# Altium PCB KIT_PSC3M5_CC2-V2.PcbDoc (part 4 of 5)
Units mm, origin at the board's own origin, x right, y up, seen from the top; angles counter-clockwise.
Board outline 131.5 x 87 mm, 6 copper layers (Top Layer, Int1 (GND), Int2 (Sign), Int3 (Sign), Int4 (PWR), Bottom Layer), stack 1.551 mm thick; 371 components, 253 nets, 1359 pads, 837 vias.
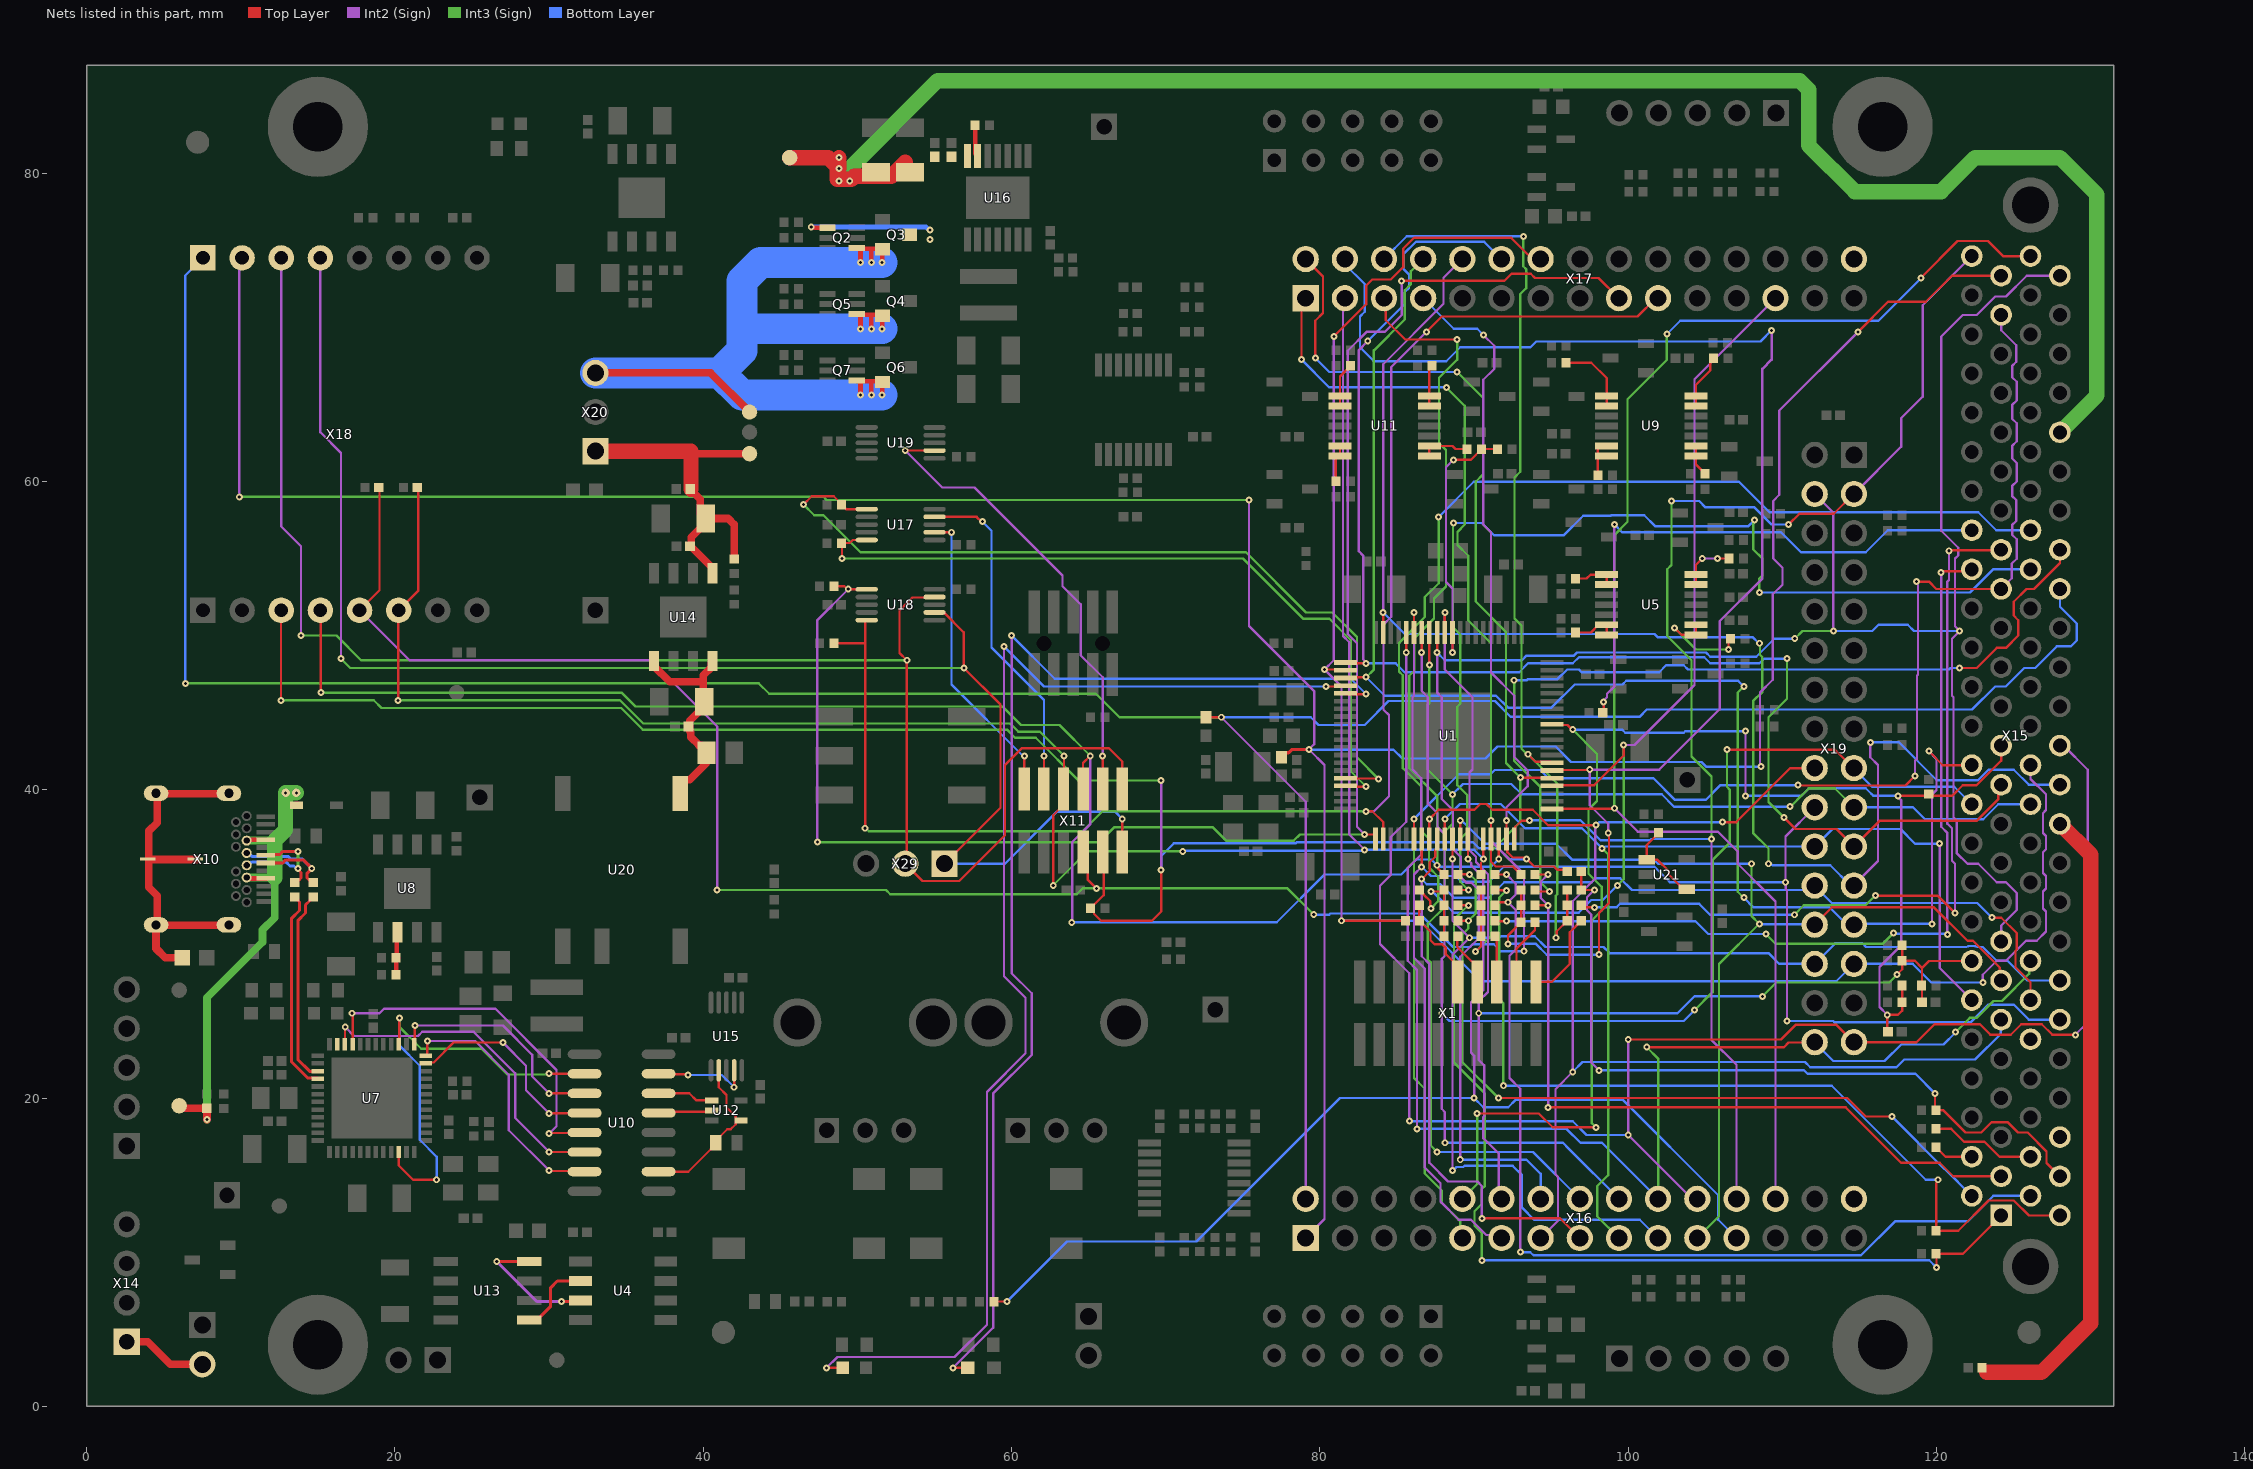
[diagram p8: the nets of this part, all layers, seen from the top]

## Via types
v1: diameter 0.45, hole 0.2, Top Layer to Bottom Layer, tented both sides, 833 vias
v2: diameter 0.55, hole 0.2, Top Layer to Bottom Layer, tented both sides, 4 vias

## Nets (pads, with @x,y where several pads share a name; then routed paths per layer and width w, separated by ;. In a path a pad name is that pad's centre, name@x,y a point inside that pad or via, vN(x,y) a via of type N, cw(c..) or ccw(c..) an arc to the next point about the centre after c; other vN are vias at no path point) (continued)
NetR135_1: R135.1 R146.2 U8.2 | length 3
  Top Layer w0.3: R146.2@20.07,28 R135.1@20.07,29.1 20.118,29.148 20.118,30.707 U8.2@20.165,30.755 U8.2@20.183,30.772 ; R135.1@20.085,29.085 20.195,29.085 R135.1@20.21,29.1
NetR140_1: R140.1 X15.A4 | length 2.6
  Top Layer w0.15: R140.1@119.97,16.8 119.97,16.78 120.185,16.565 120.205,16.565 120.575,16.195 X15.A4@122.285,16.195
NetR144_1: R144.1 X15.B4 | length 6.9
  Top Layer w0.15: R144.1@119.97,18 120.95,18 121.78,17.17 123.106,17.17 124.081,16.195 X15.B4@126.095,16.195
NetR148_1: R148.1 U21.1 U21.4 | length 5.6
  Top Layer w0.15: R148.1@101.97,37.2 101.97,37.18 101.2,36.41 U21.1@101.2,35.45 101.9,35.45 102.625,34.725 102.625,34.5 103.575,33.55 U21.4@103.8,33.55
NetU4_2: U4.2 U13.1 | length 5.1
  Top Layer w0.2: U13.1@28.7,5.595 29.2,5.595 30.1,6.495 30.1,7.7 30.535,8.135 U4.2@32.03,8.135
NetU4_3: U4.3 U13.4 | length 8.6
  Top Layer w0.2: v1(26.6,9.4) 28.695,9.4 U13.4@28.7,9.405 ; v1(30.8,6.8) 31.965,6.8 U4.3@32.03,6.865
  Int2 (Sign) w0.2: v1(26.6,9.4) 29.2,6.8 v1(30.8,6.8)
NetX14_1: X14.1 X30.2 | length 5.5
  Top Layer w0.5: X14.1@2.6,4.19 3.96,4.19 5.42,2.73 X30.2@7.5,2.73
OBD_RESET#: U7.47
OBD_RX: U7.46 U10.6 | length 21.9
  Top Layer w0.15: U7.46@16.75,23.5 16.763,23.513 16.763,24.587 v1(16.775,24.6) ; v1(30,16.5) 30.003,16.498 32.297,16.498 U10.6@32.3,16.495
  Int2 (Sign) w0.15: v1(16.775,24.6) 17.35,24.025 21.497,24.025 21.772,24.3 25.1,24.3 27.8,21.6 27.8,18.7 v1(30,16.5)
OBD_SWCLK: U7.22 U7.39 U10.2 | length 30.8
  Top Layer w0.15: U7.22@20.25,16.5 20.25,15.622 21.17,14.702 v1(22.7,14.702) ; U7.39@20.25,23.5 20.275,23.525 20.275,25.175 v1(20.3,25.2) ; v1(30,21.585) 30.005,21.58 32.295,21.58 U10.2@32.3,21.575
  Int3 (Sign) w0.15: v1(20.3,25.2) 20.3,24.6 21.7,23.2 25.6,23.2 27.275,21.525 29.94,21.525 v1(30,21.585)
  Bottom Layer w0.15: v1(20.3,25.2) 20.3,23.4 21.6,22.1 21.6,17.296 22.7,16.196 v1(22.7,14.702)
OBD_SWDIN: U7.36 U10.7 | length 16.8
  Top Layer w0.15: U7.36@22,22.75 22.025,22.75 22.1,22.825 v1(22.1,23.7) ; v1(30,15.3) 30.038,15.262 32.262,15.262 U10.7@32.3,15.225
  Int2 (Sign) w0.15: v1(22.1,23.7) 25.2,23.7 27.385,21.515 27.385,17.915 v1(30,15.3)
OBD_SWDIR: U7.37 U10.3 | length 14.9
  Top Layer w0.15: U7.37@21.25,23.5 21.275,23.525 21.275,24.675 v1(21.3,24.7) ; v1(30,20.3) 30.003,20.302 32.297,20.302 U10.3@32.3,20.305
  Int2 (Sign) w0.15: v1(21.3,24.7) 27,24.7 28.9,22.8 28.9,21.4 v1(30,20.3)
OBD_SWDOUT: U7.35 U10.4 | length 13.7
  Top Layer w0.15: U7.35@22,22.25 22.059,22.309 22.509,22.309 23.8,23.6 v1(27,23.6) ; v1(30,19) 30.018,19.018 32.283,19.018 U10.4@32.3,19.035
  Int2 (Sign) w0.15: v1(27,23.6) 28.5,22.1 28.5,20.5 v1(30,19)
OBD_TX: U7.45 U10.5 | length 23.7
  Top Layer w0.15: v1(17.2,25.5) 17.25,25.45 U7.45@17.25,23.5 ; v1(30,17.7) 30.033,17.732 32.267,17.732 U10.5@32.3,17.765
  Int2 (Sign) w0.15: v1(17.2,25.5) 19,25.5 19.3,25.8 26.5,25.8 30.475,21.825 30.475,18.175 v1(30,17.7)
OUT1A: R16.1 U5.1 U5.2 | length 7.1
  Top Layer w0.15: v1(103,50.5) 103.45,50.05 U5.1@104.4,50.05 U5.2@104.4,50.7 ; v1(106.5,49.1) 106.5,49.67 R16.1@106.63,49.8
  Int3 (Sign) w0.15: v1(103,50.5) 104.4,49.1 v1(106.5,49.1)
OUT1B: R41.1 U5.6 U5.7 | length 3.6
  Top Layer w0.15: U5.6@104.4,53.3 104.4,54.6 v1(104.8,55) ; v1(105.8,55) R41.1@106.53,55
  Int2 (Sign) w0.15: v1(104.8,55) v1(105.8,55)
OUT1C: R43.1 U5.8 U5.9 | length 2.9
  Top Layer w0.15: R43.1@96.57,53.7 97.3,53.7 97.55,53.95 U5.8@98.6,53.95 U5.9@98.6,53.3 U5.9@98.5,53.2
OUT1D: R45.1 U5.13 U5.14 | length 2.9
  Top Layer w0.15: R45.1@96.57,50.2 97.575,50.2 98.075,50.7 U5.13@98.6,50.7 U5.14@98.6,50.05
OUT2A: R55.1 U9.1 U9.2 | length 2
  Top Layer w0.15: U9.2@104.4,62.3 U9.1@104.4,61.65 104.4,61.09 104.97,60.52 R55.1@104.97,60.5
OUT2B: R57.1 U9.6 U9.7 | length 3.6
  Top Layer w0.15: U9.6@104.4,64.9 U9.7@104.4,65.55 104.4,66.275 105.315,67.19 105.315,67.785 R57.1@105.53,68
OUT2C: R59.1 U9.8 U9.9 | length 4.8
  Top Layer w0.15: R59.1@95.97,67.7 97.6,67.7 98.6,66.7 U9.8@98.6,65.55 U9.9@98.6,64.9
OUT2D: R61.1 U9.13 U9.14 | length 2.4
  Top Layer w0.15: R61.1@98.03,60.4 98.03,62.15 98.18,62.3 U9.13@98.6,62.3
OUT3A: R40.1 U11.1 U11.2 | length 3.2
  Top Layer w0.15: U11.1@87.1,61.65 U11.2@87.1,62.3 88.6,62.3 88.8,62.1 R40.1@89.53,62.1
OUT3B: R42.1 U11.6 U11.7 | length 2.7
  Top Layer w0.15: U11.6@87.1,64.9 U11.7@87.1,65.55 87.1,67.33 R42.1@87.27,67.5
OUT3C: R44.1 U11.8 U11.9 | length 2.9
  Top Layer w0.15: U11.9@81.3,64.9 U11.8@81.3,65.55 81.3,66.81 81.97,67.48 R44.1@81.97,67.5
OUT3D: R46.1 U11.13 U11.14 | length 2.5
  Top Layer w0.15: R46.1@81.03,60 81.03,61.5 81.18,61.65 U11.14@81.3,61.65 U11.13@81.3,62.3
P0_0_PFC_Relay1: R1.1 X15.A49 X16.1 X18.15 | length 206.4
  Top Layer w0.15: v1(114.9,69.7) 116.851,71.651 119.302,71.651 120.996,73.345 X15.A49@124.19,73.345
  Top Layer w0.2: R1.1@77.5,42.1 77.5,42.15 77.75,42.4 77.971,42.4 78.171,42.6 v1(79.3,42.6)
  Int2 (Sign) w0.15: v1(9.9,59) 9.9,74.32 X18.15@10.08,74.5 ; v1(75.4,58.8) 75.4,50.628 79.621,46.407 79.621,42.95 79.3,42.629 v1(79.3,42.6) 80.3,41.6 80.3,12.146 X16.1@79.312,11.158 ; v1(108.6,41.5) 108.55,41.55 108.55,46.314 109.375,47.139 109.375,52.675 110,53.3 110,54.4 109.4,55 109.4,58.728 109.8,59.128 109.8,64.6 v1(114.9,69.7)
  Int2 (Sign) w0.2: X16.1@79.076,10.922 X16.1@79.312,11.158
  Int3 (Sign) w0.15: v1(9.9,59) 47.8,59 48,58.8 v1(75.4,58.8)
  Bottom Layer w0.15: v1(79.3,42.6) 84.776,42.6 85.351,42.025 90.747,42.025 91.522,42.8 95.293,42.8 96.293,41.8 104.749,41.8 105.049,41.5 v1(108.6,41.5)
P0_1_ENPOW3: R2.2 X15.B33 X16.2 X18.16 | length 193.3
  Top Layer w0.15: R2.2@72.6,44.7 v1(73.6,44.7)
  Int2 (Sign) w0.15: v1(73.6,44.7) 79.076,39.224 X16.2@79.076,13.462
  Int3 (Sign) w0.15: v1(6.4,46.9) 43.6,46.9 44.275,46.225 65.475,46.225 67,44.7 v1(73.6,44.7)
  Bottom Layer w0.15: v1(6.4,46.9) 6.4,73.36 X18.16@7.54,74.5 ; v1(73.6,44.7) 79.4,44.7 79.9,44.2 82.9,44.2 84.45,45.75 91.35,45.75 92.375,44.725 100.725,44.725 101.2,45.2 122.3,45.2 123.8,46.7 124.482,46.7 125.682,47.9 126.4,47.9 127.8,49.3 128.7,49.3 129.1,49.7 129.1,50.764 128,51.864 X15.B33@128,53.025
P3_3_PFC_Overcurrent_Prot: U1.26 X15.A33 X15.A47 X16.9 | length 103.3
  Top Layer w0.15: U1.26@86.1,36.8 v1(86.1,38.1) ; v1(111,40.3) 111.023,40.277 117.977,40.277 v1(118.6,40.9) ; v1(118.7,53.5) 119.5,53.5 119.98,53.02 124.185,53.02 X15.A33@124.19,53.025
  Int2 (Sign) w0.15: v1(118.6,40.9) 118.6,41.876 118.725,42.001 118.725,47.397 118.8,47.472 118.8,53.305 118.7,53.405 v1(118.7,53.5) ; X15.A33@124.19,53.025 124.883,53.717 124.883,54.668 125.2,54.985 125.2,56.246 124.9,56.546 124.9,57.175 125.165,57.44 125.165,58.795 124.9,59.06 124.9,59.702 125.2,60.002 125.2,61.2 124.9,61.5 124.9,62.3 125.2,62.6 125.2,63.768 124.9,64.068 124.9,64.955 125.2,65.255 125.2,66.46 124.9,66.76 124.9,67.495 125.165,67.76 125.165,68.835 124.19,69.81 X15.A47@124.19,70.805
  Int3 (Sign) w0.15: v1(86.1,38.1) 86.1,21.3 86.8,20.6 86.8,15.1 87.9,14 87.9,13.207 89.11,11.997 89.11,11.048 X16.9@89.236,10.922
  Bottom Layer w0.15: v1(86.1,38.1) 89,41 91.068,41 91.343,41.275 94.295,41.275 94.83,40.74 101.631,40.74 103.031,39.34 105.02,39.34 105.98,40.3 v1(111,40.3)
P4_0_U1_H: U1.27 X15.B11 X16.11 X19.20 | length 87.5
  Top Layer w0.15: v1(86.6,35) U1.27@86.6,36.8
  Int2 (Sign) w0.15: v1(86.6,35) 86.1,34.5 86.1,29.1 86.8,28.4 86.8,15.5 87.821,14.479 87.821,13.286 89,12.107 89.793,12.107 90.789,11.111 91.587,11.111 X16.11@91.776,10.922 ; v1(110.3,25) 110.3,33.475 110.225,33.55 110.225,33.975 v1(110.2,34) 110.2,36.966 X19.20@112.096,38.862
  Bottom Layer w0.15: v1(86.6,35) 87.2,34.4 88.823,34.4 89.186,34.037 90.966,34.037 91.928,35 101.7,35 102.7,34 v1(110.2,34) ; v1(110.3,25) 113.295,25 113.37,24.925 122.234,24.925 123.369,26.06 125.011,26.06 125.986,25.085 X15.B11@128,25.085
P4_1_U1_L: U1.28 X15.A11 X16.13 X19.18 | length 87.3
  Top Layer w0.15: U1.28@87.1,36.7 U1.28@87.1,36.8 v1(87.1,38.1) 87.7,38.7 90.028,38.7 90.403,39.075 90.797,39.075 91.172,38.7 93.8,38.7 94.8,37.7 v1(97.9,37.7) ; v1(106.1,37.9) 107,37.9 110.502,41.402 X19.18@112.07,41.402
  Int2 (Sign) w0.15: X16.13@94.316,10.922 95.441,12.047 95.441,14.887 95.275,15.053 95.275,20.575 v1(96.4,21.7) 96.4,32.772 97.85,34.222 97.85,37.65 v1(97.9,37.7)
  Bottom Layer w0.15: v1(96.4,21.7) 97.033,22.333 111.467,22.333 111.8,22 117.4,22 117.9,22.5 122.5,22.5 124.16,24.16 124.16,25.055 X15.A11@124.19,25.085 ; v1(97.9,37.7) 97.938,37.7 98.138,37.9 v1(106.1,37.9)
P4_2_V1_H: U1.29 X15.B12 X16.15 X19.24 | length 80.7
  Top Layer w0.15: v1(86.6,34.2) 87.125,34.725 87.125,35.297 87.475,35.647 87.475,36.075 87.6,36.2 U1.29@87.6,36.8 ; v1(90.5,12.2) 95.578,12.2 X16.15@96.856,10.922 ; v1(123.6,31.7) 124.2,31.7 125.2,30.7 125.2,29.632 125.12,29.552 125.12,28.484 126.095,27.509 X15.B12@126.095,26.355
  Int2 (Sign) w0.15: v1(86.6,34.2) 86.6,29.2 87.1,28.7 87.1,15.8 88.313,14.587 90.213,14.587 90.5,14.3 v1(90.5,12.2)
  Bottom Layer w0.15: v1(86.6,34.2) 86.925,33.875 87.825,33.875 88.7,33 90.954,33 91.954,34 97.628,34 97.878,34.25 99.486,34.25 100.236,33.5 111.788,33.5 112.07,33.782 113.195,32.657 122.643,32.657 v1(123.6,31.7)
P4_3_V1_L: U1.30 X15.A12 X16.17 X19.22 | length 73.2
  Top Layer w0.15: U1.30@88.1,36.8 v1(88.1,38.1)
  Int2 (Sign) w0.15: v1(120.2,36.5) 120.2,28.44 X15.A12@122.285,26.355
  Int3 (Sign) w0.15: v1(98.3,36.2) 98.7,35.8 98.7,15 97.981,14.281 97.981,12.337 X16.17@99.396,10.922
  Bottom Layer w0.15: v1(88.1,38.1) 88.5,38.5 88.504,38.5 89.079,39.075 91.725,39.075 93.3,37.5 97,37.5 v1(98.3,36.2) ; v1@98.381,36.2 98.503,36.322 112.122,36.322 113.247,37.447 117.653,37.447 118.6,36.5 v1(120.2,36.5)
P4_4_W1_H: U1.31 X15.B13 X16.19 X19.28 | length 79.7
  Top Layer w0.15: v1(88.6,35.5) U1.31@88.6,36.8
  Int2 (Sign) w0.15: v1(88.6,15.3) 88.6,29.3 v1(89.7,30.4) 88.6,31.5 v1(88.6,35.5)
  Bottom Layer w0.15: v1(88.6,15.3) 88.638,15.3 88.863,15.525 89.297,15.525 89.372,15.6 92.5,15.6 93.1,15 93.1,12.9 93.893,12.107 100.751,12.107 X16.19@101.879,10.979 ; v1(89.7,30.4) 91.644,30.4 91.744,30.5 93.932,30.5 94.632,29.8 98.395,29.8 98.795,29.4 109.1,29.4 109.798,28.702 X19.28@112.07,28.702 ; X16.19@101.9,11 101.936,10.964 X16.19@101.936,10.922 ; X19.28@112.096,28.702 113.435,30.041 115.175,30.041 115.417,29.8 121.922,29.8 cw(c122.285,28.895) 122.648,29.8 123,29.8 123.9,28.9 124.6,28.9 125.875,27.625 X15.B13@128,27.625
P4_5_W1_L: U1.32 X15.A13 X16.21 X19.26 | length 66
  Top Layer w0.15: U1.32@89.1,36.8 v1(89.1,38) ; X19.26@112.07,31.242 113.195,32.367 119.833,32.367 122,30.2 122.359,30.2 124.097,28.462 124.097,27.718 X15.A13@124.19,27.625
  Int3 (Sign) w0.15: X16.21@104.476,10.922 105.891,12.337 105.891,28.691 v1(108.5,31.3) 108,31.8 v1(108,35.2)
  Bottom Layer w0.15: v1(89.1,38) 89.195,38 89.331,37.864 89.336,37.864 90.7,36.5 95.328,36.5 96.378,35.45 101.674,35.45 101.924,35.2 v1(108,35.2) ; v1(108.5,31.3) 108.529,31.271 112.041,31.271 X19.26@112.07,31.242
P7_0_SCB2_CLK: R60.1 R81.1 X15.A2 | length 50.9
  Top Layer w0.15: R60.1@88.95,31.5 v1(89.625,31.5) ; R81.1@88.95,34.5 88.962,34.512 v1(89.712,34.512) ; v1(91.575,20) 114.2,20 115.4,18.8 v1(117.1,18.8)
  Int2 (Sign) w0.15: v1(89.712,34.512) v1@89.779,34.446
  Int3 (Sign) w0.15: v1(89.712,34.512) 90.1,34.125 90.1,31.975 v1(89.625,31.5) 89.625,30.997 89.25,30.622 89.25,22.325 v1(91.575,20)
  Bottom Layer w0.15: v1(117.1,18.8) 120.5,15.4 120.54,15.4 X15.A2@122.285,13.655
P7_0_SCB2_SCL: R56.1 R141.1 X15.A1 | length 61.2
  Top Layer w0.15: R56.1@88.95,32.5 v1(89.625,32.5) ; v1(120,9) 120,9.87 R141.1@119.97,9.9 121.705,9.9 X15.A1@124.19,12.385
  Int3 (Sign) w0.15: v1(89.625,32.5) 88.7,31.575 88.7,22.3 90.7,20.3 90.7,14.3 90.5,14.1 90.5,13.133 90.025,12.658 90.025,11.724 90.5,11.249 v1(90.5,9.475)
  Bottom Layer w0.15: v1(90.5,9.475) 119.525,9.475 v1(120,9)
P7_0_U3_H/PFC_PWM_A_1: R88.1 X15.B34 | length 69.6
  Top Layer w0.15: R88.1@88.95,33.5 v1(89.625,33.5) ; X15.B34@126.09,54.29 X15.B34@126.095,54.295
  Int3 (Sign) w0.15: v1(88.65,57.3) 88.625,57.275 88.625,50.547 89.1,50.072 89.1,45.586 88.9,45.386 88.9,40.3 89.55,39.65 89.55,37.25 89.1,36.8 89.1,34.025 v1(89.625,33.5) ; v1(108.2,57.5) 108.133,57.433 108.133,57.27 108.1,57.237 108.1,55.604 108.7,55.004 108.7,53.903 108.5,53.703 v1(108.5,52.8)
  Bottom Layer w0.15: v1(88.65,57.3) 90.5,57.3 91.3,56.5 95.8,56.5 97.075,57.775 98.629,57.775 98.878,57.775 98.903,57.8 101.031,57.8 101.731,57.1 107.8,57.1 v1(108.2,57.5) ; v1(108.5,52.8) 122.169,52.8 123.664,54.295 X15.B34@126.095,54.295
P7_1_SCB2_MOSI: R62.1 R82.1 X15.B2 | length 62.2
  Top Layer w0.15: R62.1@91.35,32.4 91.35,32.475 91.575,32.7 v1(92.2,32.7) ; R82.1@91.35,34.5 v1(92.1,34.5)
  Int2 (Sign) w0.15: v1(92.1,34.5) 92.7,33.9 92.7,33.2 v1(92.2,32.7) 92.7,32.2 92.7,29.628 92.3,29.228 92.3,21.3 93,20.6 v1(93,10)
  Bottom Layer w0.15: v1(93,10) 93.647,10 93.85,9.797 115.102,9.797 117.305,12 122.016,12 123.671,13.655 X15.B2@126.095,13.655
P7_1_SCB2_SDA: R58.1 R142.1 X15.B1 | length 57.1
  Top Layer w0.15: R58.1@91.35,33.5 91.378,33.472 v1(92.098,33.472) ; v1(120.1,14.7) 120.1,14.605 119.97,14.475 R142.1@119.97,11.4 121.4,11.4 121.408,11.392 123.376,13.36 125.011,13.36 125.986,12.385 X15.B1@128,12.385
  Int3 (Sign) w0.15: v1(91.9,20.8) 91.9,26.144 91.623,26.42 91.623,32.997 v1(92.098,33.472)
  Bottom Layer w0.15: v1(91.9,20.8) 113.2,20.8 119.3,14.7 v1(120.1,14.7)
P7_1_U3_L/PFC_PWM_A_2: R89.1 X15.A34 | length 56
  Top Layer w0.15: R89.1@91.35,31.5 91.378,31.472 v1(92.098,31.472) ; v1(120.3,54.1) 120.367,54.167 122.157,54.167 X15.A34@122.285,54.295
  Int2 (Sign) w0.15: v1(120.3,54.1) 120.3,37.6 120.7,37.2 v1(120.7,30.6)
  Int3 (Sign) w0.15: v1(108.925,30.643) 109.568,30 116.5,30 v1(117.2,30.7)
  Bottom Layer w0.15: v1(92.098,31.472) 104.356,31.472 105.185,30.643 v1(108.925,30.643) ; v1(117.2,30.7) 117.25,30.65 120.65,30.65 v1(120.7,30.6)
P7_2_SCB2_MISO: R74.1 R83.1 X15.A3 | length 48.4
  Top Layer w0.15: R74.1@93.95,32.5 v1(94.8,32.5) ; R83.1@93.95,34.5 v1(94.8,34.5) ; v1(94.8,19.4) 114.1,19.4 117.7,15.8 120.2,15.8 121.075,14.925 X15.A3@124.19,14.925
  Int2 (Sign) w0.15: v1(94.8,19.4) v1(94.8,32.5) 94.325,32.975 94.325,34.025 v1(94.8,34.5)
P7_2_V3_H/PFC_PWM_B_1: R90.1 X15.B35 | length 57.1
  Top Layer w0.15: R90.1@93.95,33.5 94.05,33.4 v1(94.9,33.4) ; v1(121.5,47.9) 122.6,47.9 123.9,49.2 124.5,49.2 125.3,50 125.3,51 125,51.3 125,52.2 125.825,53.025 126.325,53.025 128,54.7 X15.B35@128,55.565
  Int3 (Sign) w0.15: v1(92.6,47.1) 92.6,41.872 94.3,40.172 94.3,34 v1(94.9,33.4)
  Bottom Layer w0.15: v1(92.6,47.1) 93.428,47.1 93.503,47.175 95.412,47.175 96.037,47.8 96.8,47.8 96.975,47.625 102.003,47.625 102.453,48.075 103.597,48.075 103.872,47.8 120.8,47.8 120.9,47.9 v1(121.5,47.9)
P7_3_SCB2_SEL0: R76.1 R87.1 R143.1 X15.B3 | length 48.6
  Top Layer w0.15: R87.1@96.95,34.7 R76.1@96.95,33.5 v1(97.8,33.5) ; v1(119.9,20.3) 119.9,19.27 R143.1@119.97,19.2 120.441,19.2 121.881,17.76 122.898,17.76 123.577,18.44 124.594,18.44 125.274,17.76 125.909,17.76 127.13,16.539 127.13,15.795 X15.B3@128,14.925
  Int2 (Sign) w0.15: v1(97.8,33.5) 97.325,33.025 97.325,32.176 97.6,31.901 97.6,22.3 v1(98.1,21.8)
  Bottom Layer w0.15: v1(98.1,21.8) 111.4,21.8 111.625,21.575 118.625,21.575 v1(119.9,20.3)
P7_3_V3_L/PFC_PWM_B_2: R92.1 X15.A35 | length 52.8
  Top Layer w0.15: R92.1@96.95,32.5 97.078,32.372 v1(97.8,32.372) ; v1(116.025,33.132) 120.068,33.132 v1(121.2,32) ; v1(120.8,55.5) 120.832,55.533 124.158,55.533 X15.A35@124.19,55.565 X15.A35@124.185,55.57
  Int2 (Sign) w0.15: v1(120.8,55.5) 120.8,53.6 120.7,53.5 120.7,37.8 121,37.5 121,35.4 121.2,35.2 v1(121.2,32)
  Int3 (Sign) w0.15: v1(110.775,31.892) 111.383,32.5 115.393,32.5 v1(116.025,33.132)
  Bottom Layer w0.15: v1(97.8,32.372) 99.244,32.372 99.472,32.6 104.597,32.6 105.305,31.892 v1(110.775,31.892)
P7_4_W3_H/PFC_PWM_C_1: R97.1 X15.B36 | length 70
  Top Layer w0.15: R97.1@86.363,33.587 R97.1@86.45,33.5 86.725,33.225 86.725,33.203 87.153,32.775 87.153,32.347 v1(87.2,32.3)
  Int3 (Sign) w0.15: v1(87.2,32.3) 87.675,32.775 87.675,34.353 87.075,34.953 87.075,36.825 86.575,37.325 86.575,40.201 85.375,41.401 85.375,47.425 85.125,47.675 85.125,49.525 86.8,51.2 86.8,52.5 87.7,53.4 v1(87.7,57.7)
  Bottom Layer w0.15: v1(87.7,57.7) 89.975,59.975 107.182,59.975 109.157,58 122.7,58 123.865,56.835 X15.B36@126.095,56.835
P7_5_W3_L/PFC_PWM_C_2: R98.1 X15.A36 | length 37
  Top Layer w0.15: R98.1@98.35,45 98.4,45.05 v1(98.4,45.7)
  Int2 (Sign) w0.15: v1(98.4,45.7) 98.4,45.781 98.621,46.002 98.621,46.221 99.1,46.7 v1(99.1,57.2)
  Bottom Layer w0.15: v1(99.1,57.2) 99.6,56.7 109.9,56.7 111.2,55.4 115.4,55.4 116.835,56.835 X15.A36@122.285,56.835
P7_7_KILL_2: C138.1 R32.1 R36.2 R162.1 U1.52 X15.A25 X16.10 | length 96.2
  Top Layer w0.15: v1(90.2,19) 94.2,19 95.1,18.1 v1(97.9,18.1) ; U1.52@95.225,44.275 95.306,44.194 96.057,44.194 96.351,43.9 v1(96.4,43.9) ; C138.1@116.86,24.3 116.8,24.36 v1(116.8,25.4) 117.5,25.4 117.77,25.67 R36.2@117.77,27.3 ; v1(117.5,39.6) 119.37,39.6 R162.1@119.5,39.73 119.63,39.6 121,39.6 121.694,40.294 122.594,40.294 124.19,41.89 X15.A25@124.19,42.865
  Int2 (Sign) w0.15: v1(107.6,39.6) v1(107.6,43.8) ; v1(116.8,25.4) 116.3,25.9 116.3,28.5 117.7,29.9 117.7,39.337 117.5,39.537 v1(117.5,39.6)
  Int3 (Sign) w0.15: X16.10@89.236,13.462 90.2,14.426 v1(90.2,19) ; v1(96.4,43.9) 97.975,42.325 97.975,39.275 97.425,38.725 97.425,34.547 98.275,33.697 98.275,32.176 97.625,31.526 97.625,18.375 v1(97.9,18.1)
  Bottom Layer w0.15: v1(96.4,43.9) 99.6,43.9 99.8,43.7 103.603,43.7 103.703,43.8 v1(107.6,43.8) ; v1(107.6,39.6) 111.217,39.6 111.717,40.1 115.4,40.1 115.764,39.736 115.769,39.736 115.905,39.6 v1(117.5,39.6)
P8_0_KILL_1: C139.1 R33.2 R37.2 R163.1 U1.71 X15.A14 X16.12 | length 79
  Top Layer w0.15: U1.71@88.1,50.2 v1(88.1,51.5) ; v1(117.444,28.008) 117.444,28.027 117.77,28.354 R37.2@117.77,28.9 ; R33.2@117.77,29.9 R37.2@117.77,28.9 ; R163.1@119.003,27.327 R163.1@119.03,27.3 R163.1@119.06,27.27 ; C139.1@119.06,26.2 R163.1@119.06,27.27 ; X15.A14@122.285,28.895 119.515,28.895 119.06,28.44 ; R37.2@117.77,28.9 118.6,28.9 119.06,28.44 ; R163.1@119.06,27.27 119.06,28.44
  Int2 (Sign) w0.15: v1(88.1,51.5) 88.1,47.8 89.9,46 89.9,41.314 89.7,41.114 89.7,36.072 90.125,35.647 90.125,35.303 90.6,34.828 90.6,34.824 90.9,34.524 90.9,26.876 90.3,26.276 90.3,22.471 90.65,22.121 90.65,18.814 90.6,18.764 90.6,17.4 91.6,16.4 91.6,13.638 X16.12@91.776,13.462
  Int3 (Sign) w0.15: v1(108.7,26.6) 109.6,27.5 116.935,27.5 v1(117.444,28.008)
  Bottom Layer w0.15: v1(90.3,25.5) 103.2,25.5 104.3,26.6 v1(108.7,26.6)
P8_1_PFC_Relay2: U1.72 X15.A15 X15.B49 X16.14 X19.4 | length 140.4
  Top Layer w0.15: v1(87.6,48.9) U1.72@87.6,50.2
  Int2 (Sign) w0.15: v1(87.6,48.9) 87.6,46.3 87.9,46 87.9,39.4 88.625,38.675 88.625,36.147 89.125,35.647 89.125,34.338 89.488,33.975 89.822,33.975 90.3,33.497 90.3,30.45 90.3,30.364 89.1,29.164 v1(89.1,16) ; X19.4@112.096,59.182 113.3,57.978 v1(113.3,50.3) ; X15.A15@124.19,30.165 124.19,31.19 125.2,32.2 125.2,33.3 124.5,34 123.9,34 122.7,35.2 122,35.2 121.3,35.9 121.3,38 121.1,38.2 121.1,46 121,46.1 121,49.8 v1(121.5,50.3) 121.2,50.6 121.2,55 121.4,55.2 121.4,55.7 120.3,56.8 120.3,69.4 121.7,70.8 122.6,70.8 123.8,72 124.5,72 125.845,73.345 X15.B49@128,73.345
  Int3 (Sign) w0.15: v1(110.8,49.8) 111.3,50.3 v1(113.3,50.3)
  Bottom Layer w0.15: v1(87.6,48.9) 88.1,48.4 93.1,48.4 93.4,48.7 96.476,48.7 96.676,48.9 105.049,48.9 105.324,48.625 108.297,48.625 109.472,49.8 v1(110.8,49.8) ; v1(89.1,16) 93.4,16 94.316,15.084 X16.14@94.316,13.462 ; v1(113.3,50.3) 115.827,50.3 116.227,50.7 118.133,50.7 118.533,50.3 v1(121.5,50.3)
P8_2_U2_H: U1.73 X15.B22 X16.16 X19.19 | length 86.1
  Top Layer w0.15: v1(87.1,48.1) U1.73@87.1,50.2
  Int3 (Sign) w0.15: v1(87.1,48.1) 87.1,45.586 87,45.486 87,41.314 88.6,39.714 88.6,37.771 88.1,37.271 88.1,32.4 87,31.3 87,29 87.2,28.8 87.2,16.9 v1(87.6,16.5) ; v1@110.512,38.888 110.945,39.321 110.945,39.328 111.717,40.1 113.398,40.1 X19.19@114.636,38.862
  Bottom Layer w0.15: v1(87.6,16.5) 93.818,16.5 X16.16@96.856,13.462 ; v1@88.522,39.622 89.275,40.375 92.414,40.375 93.089,39.7 102.172,39.7 102.972,38.9 v1(110.5,38.9) ; X19.19@114.61,38.862 118.468,38.862 119.25,38.08 123.025,38.08 124,39.055 X15.B22@126.095,39.055
  other v1: 88.6,39.7
P8_3_U2_L: U1.74 X15.A22 X16.18 X19.17 | length 98.8
  Top Layer w0.15: v1(86.6,48.9) U1.74@86.6,50.2 ; v1(106.4,42.6) 113.412,42.6 X19.17@114.61,41.402
  Int2 (Sign) w0.15: v1(86.6,48.9) 86.6,46.4 87,46 87,39.1 87.625,38.475 87.625,37.575 88.075,37.125 88.075,35.297 88.075,29.203 87.9,29.028 87.9,19.3 88.1,19.1 v1(88.1,17.1)
  Int3 (Sign) w0.15: v1(104.3,25.7) 105.471,26.871 105.471,35.443 106.575,36.547 106.575,40.017 106.4,40.192 v1(106.4,42.6)
  Bottom Layer w0.15: v1(87.9,25.5) 88.4,25 103.6,25 v1(104.3,25.7) ; v1(88.1,17.1) 95.758,17.1 96.158,16.7 X16.18@99.396,13.462 ; X19.17@114.61,41.402 115.812,40.2 121.14,40.2 X15.A22@122.285,39.055
P8_4_ENPOW1: U1.75 X15.B14 X16.20 X19.32 | length 92
  Top Layer w0.15: U1.75@86.1,50.2 v1(86.1,51.5) ; v1(101.2,23.3) 110.1,23.3 110.4,23.6 112.048,23.6 X19.32@112.07,23.622
  Int2 (Sign) w0.15: v1(86.1,51.5) 86.1,46.1 86,46 86,41.314 86.575,40.739 86.575,35.803 85.7,34.928 85.7,28.9 86.3,28.3 v1(86.3,18)
  Int3 (Sign) w0.15: v1(101.2,23.3) 101.936,22.564 X16.20@101.936,13.462 ; v1(121.23,24.274) 122.157,25.2 122.6,25.2 123.7,26.3 124.244,26.3 126.002,28.058 126.002,28.802 X15.B14@126.095,28.895
  Bottom Layer w0.15: v1(86.3,18) 96,18 96.9,17.1 98.298,17.1 X16.20@101.936,13.462 ; X19.32@112.07,23.622 113.292,22.4 116.628,22.4 117.703,23.475 120.451,23.475 v1@121.24,24.264
P8_5_ENPOW2: U1.76 X15.B25 X16.22 X19.31 | length 111.4
  Top Layer w0.15: v1(85.6,48.9) U1.76@85.6,50.2 ; v1(100,23.8) 109.9,23.8 110.847,24.747 113.511,24.747 X19.31@114.636,23.622 ; X19.31@114.61,23.622 118.694,23.622 119.862,24.79 122.81,24.79 123.49,24.11 124.81,24.11 125.49,24.79 126.82,24.79 127.51,24.1 v1(129,24.1)
  Int2 (Sign) w0.15: v1(85.6,48.9) 85.6,37.928 84.6,36.928 84.6,34.476 83.9,33.776 83.9,30 85.8,28.1 v1(85.8,18.5) ; v1(100,23.8) v1(100,17.6) 104.138,13.462 X16.22@104.476,13.462 ; X15.B25@128,42.865 128.235,42.865 129.8,41.3 129.8,24.9 v1(129,24.1)
  Bottom Layer w0.15: v1(85.8,18.5) 96.4,18.5 97.3,17.6 v1(100,17.6)
P9_0_V2_H: U1.79 X15.B23 X17.10 X19.23 | length 96.9
  Top Layer w0.15: U1.79@84.1,50.2 v1(84.1,51.5)
  Int2 (Sign) w0.15: v1(84.1,51.5) 84.1,67.6 88.02,71.52 88.02,73.206 X17.10@89.236,74.422 ; X19.23@114.61,33.782 116.2,35.372 116.2,41.604 115.7,42.104 v1(115.7,43.075)
  Int3 (Sign) w0.15: v1(108.5,49.5) 108.546,49.454 108.546,48.75 108.7,48.596 108.7,46.347 108.1,45.747 108.1,37.2 109.1,36.2 v1(109.1,35.2)
  Bottom Layer w0.15: v1(84.1,51.5) 85.5,50.1 101.7,50.1 101.9,49.9 108.062,49.9 108.462,49.5 v1(108.5,49.5) ; v1(109.1,35.2) 109.167,35.133 109.33,35.133 109.363,35.1 113.1,35.1 114.418,33.782 X19.23@114.636,33.782 ; v1(115.7,43.075) 117.553,43.075 120.008,40.62 122.689,40.62 123.369,41.3 125.011,41.3 125.986,40.325 X15.B23@128,40.325
P9_1_V2_L: U1.1 X15.A23 X17.12 X19.21 | length 93.1
  Top Layer w0.15: U1.1@81.7,48.2 v1(83,48.2) ; v1(110.1,38.2) 110.853,37.447 113.511,37.447 X19.21@114.636,36.322 116.294,37.98 122.589,37.98 124.009,39.4 124.009,40.144 X15.A23@124.19,40.325
  Int2 (Sign) w0.15: v1(83,48.2) 83,48.263 82.8,48.463 82.8,55.2 82.525,55.475 82.525,68.525 v1(83.1,69.1)
  Int3 (Sign) w0.15: v1(110.1,38.2) 109.1,39.2 109.1,44.7 110.3,45.9 v1(110.3,48.5)
  Bottom Layer w0.15: v1(83,48.2) 84.908,48.2 85.483,47.625 92.925,47.625 93.5,48.2 96.4,48.2 96.8,48.6 104.924,48.6 105.324,48.2 108.506,48.2 108.806,48.5 v1(110.3,48.5) ; v1(83.1,69.1) 85.504,71.504 85.504,72.281 85.775,72.552 85.775,73.427 85.426,73.776 85.426,74.743 86.23,75.547 90.651,75.547 X17.12@91.776,74.422
P9_2_W2_H: R25.1 U1.2 X15.B24 X17.14 X19.27 | length 123.8
  Top Layer w0.15: v1(80.3,47.8) U1.2@81.6,47.8 ; v1(80.9,69.4) 83,71.5 83,72.7 83.4,73.1 84.6,73.1 85.4,73.9 85.4,75.1 86.1,75.8 92.4,75.8 93.481,74.719 94.019,74.719 X17.14@94.316,74.422 ; v1(81.4,31.5) R25.1@85.55,31.5
  Int2 (Sign) w0.15: v1(80.9,69.4) 80.9,48.4 v1(80.3,47.8) 81.4,46.7 v1(81.4,31.5) ; v1(123,27.5) 123,28 123.9,28.9 124.5,28.9 125.8,30.2 126.5,30.2 127.1,30.8 127.1,32.1 126.9,32.3 126.9,33.401 127.1,33.601 127.1,34.4 126.9,34.6 126.9,35.941 127.1,36.141 127.1,37 126.9,37.2 126.9,38.481 127.1,38.681 127.1,39.7 126.095,40.705 X15.B24@126.095,41.595
  Bottom Layer w0.15: v1(81.4,31.5) 86.5,31.5 90.423,27.577 113.485,27.577 114.61,28.702 118.451,28.702 119.653,27.5 v1(123,27.5)
P9_3_W2_L: U1.3 X15.A24 X17.8 X19.25 | length 97.8
  Top Layer w0.15: U1.3@81.7,47.3 v1(83,47.3) ; v1(119.5,42.5) 120.405,41.595 X15.A24@122.285,41.595
  Int2 (Sign) w0.15: v1(119.5,42.5) 120,42 120,39.984 119.7,39.684 v1(119.7,31.3)
  Int3 (Sign) w0.15: v1(83,47.3) 83.5,47.8 83.5,68.5 85.5,70.5 85.5,72.4 85.9,72.8 85.9,73.626 X17.8@86.696,74.422 ; v1(107.5,33) 107.478,33 107.1,33.378 107.1,46.3 v1(107.5,46.7)
  Bottom Layer w0.15: v1(83,47.3) 84.2,46.1 91.424,46.1 92.199,45.325 95.025,45.325 96.525,46.825 99.625,46.825 99.875,47.075 107.125,47.075 v1(107.5,46.7) ; v1(107.5,33) 108.133,32.367 113.066,32.367 114.191,31.242 114.61,31.242 114.668,31.3 v1(119.7,31.3)
"PFC _Gate2": U1.41 X15.B50 X16.26 | length 95.5
  Top Layer w0.15: U1.41@95.05,38.75 95.075,38.775 99.075,38.775 v1(99.1,38.8) ; v1(119,73.2) 119,73.228 121.362,75.59 123.331,75.59 124.306,74.615 X15.B50@126.095,74.615
  Int2 (Sign) w0.15: v1(99.1,38.8) 100.625,37.275 105.825,37.275 107.1,36 107.1,35.2 109.556,32.744 X16.26@109.556,13.462
  Int3 (Sign) w0.15: v1(99.1,38.8) 99.1,56.528 99.953,57.381 99.953,65.325 102.5,67.872 v1(102.5,69.55)
  Bottom Layer w0.15: v1(102.5,69.55) 103.375,70.425 116.225,70.425 v1(119,73.2)
"PFC_ Gate1": U1.39 X15.A50 X16.24 X19.3 | length 93.4
  Top Layer w0.15: U1.39@92.6,36.8 92.675,36.875 92.675,37.593 93.075,37.993 93.593,37.993 v1(93.6,38) ; v1(110.4,57.2) 111.1,57.9 113.328,57.9 X19.3@114.61,59.182
  Int2 (Sign) w0.15: v1(105.4,36.8) 105.4,23.772 107.016,22.156 X16.24@107.016,13.462 ; X19.3@114.636,59.182 117.7,62.246 117.7,64.1 119.1,65.5 119.1,71.43 X15.A50@122.285,74.615
  Int3 (Sign) w0.15: v1(102.8,58.725) 102.8,54.583 102.525,54.308 102.525,49.975 104.1,48.4 104.1,42.16 105.4,40.86 v1(105.4,36.8)
  Bottom Layer w0.15: v1(93.6,38) 93.625,38.025 96.903,38.025 98.203,36.725 101.417,36.725 101.492,36.8 v1(105.4,36.8) ; v1(102.8,58.725) 104.603,58.725 105.014,58.314 108.186,58.314 109.3,57.2 v1(110.4,57.2)
PWR_IN_5V: Q2.1 Q3.3 X15.B5 X15.B10 X16.30 X17.30 | length 8.9
  Top Layer w0.3: v1(47,76.5) 47.05,76.45 Q2.1@48.05,76.45
  Bottom Layer w0.3: v1(47,76.5) 54.459,76.5 54.659,76.3 v1(54.7,76.3)
  other v1: 54.7,75.7
PWR_IN_24V: C100.2 C101.2 C102.1 C103.2 R107.2 TP5.1 U16.6 U16.7 X15.B41 | length 118.1
  Top Layer w0.3: C103.2@54.959,81.019 C103.2@55,81.06 ; R107.2@57.63,83.1 57.63,81.25 57.78,81.1 U16.6@57.8,81.1
  Top Layer w1: TP5.1@45.6,81 48.1,81 48.45,80.65 ; v1@48.7,80.3 48.7,79.6 49.6,79.6 49.8,79.8 52.2,79.8 53.1,80.7 ; v1(48.8,80.3) v1(48.8,81)
  Int3 (Sign) w1: 49.5,80.3 55.2,86 111.114,86 111.7,85.414 111.7,81.8 114.7,78.8 120.3,78.8 122.5,81 128,81 130.4,78.6 130.4,65.585 X15.B41@128,63.185
  other v1: 48.8,79.5 49.5,79.5
PWR_OUT_SYS: R47.1 X15.B21 | length 41.7
  Top Layer w0.5: R47.1@122.95,2.5 123.25,2.2
  Top Layer w1: 123.25,2.2 126.8,2.2 130,5.4 130,35.785 X15.B21@128,37.785
SPI1_CLK_P7: R12.1 R56.2 R60.2 R88.2 U1.44 X17.25 | length 66.2
  Top Layer w0.15: v1(87.2,33.4) 87.95,33.4 R88.2@88.05,33.5 R56.2@88.05,32.5 R60.2@88.05,31.5 R12.1@88.05,30.5 ; U1.44@95.05,40.25 95.1,40.3 97.8,40.3 99.7,42.2 v1(99.7,42.9)
  Int2 (Sign) w0.15: v1(99.7,42.9) 100.4,42.9 104.3,46.8 104.3,66.626 X17.25@109.556,71.882
  Int3 (Sign) w0.15: v1(99.3,33.8) 99.7,34.2 v1(99.7,42.9)
  Bottom Layer w0.15: v1(87.2,33.4) 87.295,33.4 87.431,33.264 87.436,33.264 88.675,32.025 96.781,32.025 97.603,32.847 98.347,32.847 v1@99.289,33.789
SPI1_CS0_P7: R26.1 R76.2 R92.2 U1.47 X17.6 | length 62
  Top Layer w0.15: v1(93.5,42.3) 93.98,41.82 94.93,41.82 U1.47@95.025,41.725 ; v1(95.3,30.4) 95.367,30.467 95.367,30.817 R26.1@96.05,31.5 R92.2@96.05,32.5 R76.2@96.05,33.5
  Int3 (Sign) w0.15: v1(93.2,75.9) 93.191,75.891 93.191,73.956 93.375,73.772 93.375,72.532 93,72.157 93,60.628 92.625,60.253 92.625,51.103 93.075,50.653 93.075,42.653 93.428,42.3 v1(93.5,42.3) 95.4,40.4 95.4,33.228 95.3,33.128 v1(95.3,30.4)
  Bottom Layer w0.15: X17.6@84.156,74.422 85.634,75.9 v1(93.2,75.9)
SPI1_MISO_P7: R72.1 R74.2 R90.2 U1.46 X17.4 | length 95.5
  Top Layer w0.15: v1(92.2,30) 92.2,30.55 R72.1@93.05,31.4 ; R90.2@93,33.55 R90.2@93.05,33.5 R74.2@93.05,32.5 ; R72.1@93.05,31.5 R74.2@93.05,32.4 ; U1.46@95.125,41.275 97.475,41.275 v1(97.5,41.3) ; v1(98.1,29.3) 98.1,32.001 98.75,32.651 98.75,37.15 v1(98.7,37.2)
  Int2 (Sign) w0.15: v1(98.7,37.2) 98.7,37.8 97.5,39 v1(97.5,41.3) 102,41.3 105.925,45.225 105.925,50.925 108.7,53.7 108.7,67.3 109.3,67.9 v1(109.3,69.8)
  Bottom Layer w0.15: X17.4@81.616,74.422 81.616,74.084 82.9,72.8 82.9,71 82.6,70.7 82.6,68.7 83.5,67.8 88.2,67.8 89.1,68.7 93.651,68.7 94.026,69.075 108.575,69.075 v1(109.3,69.8) v1@109.35,69.85 ; v1(92.2,30) 94.008,30 94.708,29.3 v1(98.1,29.3)
SPI1_MOSI_P7: R17.1 R58.2 R62.2 R89.2 U1.45 X17.2 | length 63.7
  Top Layer w0.15: X17.2@79.076,74.422 80.201,73.297 80.201,70.918 79.7,70.417 v1(79.7,68) ; v1(90.1,29.5) 90.45,29.85 R89.2@90.45,31.5 R58.2@90.45,33.5 ; v1(93,40.8) 93.025,40.775 94.925,40.775 U1.45@94.95,40.75
  Int3 (Sign) w0.15: v1(88.9,67.1) 90.575,65.425 90.575,60.447 90.1,59.972 90.1,52.208 92.075,50.233 92.075,41.725 v1(93,40.8) 93,37.9 91.075,35.975 91.075,30.475 90.6,30 v1(90.1,29.5)
  Bottom Layer w0.15: v1(79.7,68) 80.6,67.1 v1(88.9,67.1)
SWDCLK_S: U10.15 U15.4 | length 6.6
  Top Layer w0.15: U10.15@36.9,21.5 36.938,21.538 38.963,21.538 v1(39,21.5) ; v1(42,20.7) U15.4@42,21.8
  Bottom Layer w0.15: v1(39,21.5) 41.2,21.5 v1(42,20.7)
SWDIO_S: R53.1 U10.10 U12.4 U15.2 | length 10.8
  Top Layer w0.15: U10.10@37.1,15.225 39.025,15.225 40.48,16.68 40.525,16.68 40.81,16.965 40.81,17.235 41.548,17.973 41.773,17.973 42.1,18.3 42.1,18.425 U12.4@42.225,18.55 ; U15.2@41,21.8 41,20.7 41.5,20.2 41.5,19.4 42.1,18.8 42.1,18.675 U12.4@42.225,18.55 ; U12.4@42.45,18.55 U12.4@42.35,18.55 ; U12.4@42.225,18.55 U12.4@42.35,18.55 ; U12.4@42.225,18.55 U12.4@42.35,18.55
SWDIR_S: U10.14 U12.1 | length 3.6
  Top Layer w0.15: U10.14@37.1,20.305 39.095,20.305 39.55,19.85 U12.1@40.55,19.85
SWDOUT_S: U10.13 U12.2 | length 3.5
  Top Layer w0.15: U10.13@37.1,19.035 37.183,19.118 40.468,19.118 U12.2@40.55,19.2
TB_CLK: R81.2 U1.37 X11.8 X17.5 X18.4 | length 145.7
  Top Layer w0.15: X18.4@15.16,51.64 15.18,51.62 15.18,46.32 v1(15.2,46.3) ; X11.8@64.635,40.035 64.635,41.735 v1(65.1,42.2) ; X17.5@84.156,71.882 84.275,71.763 84.275,70.453 85.528,69.2 v1(88.9,69.2) ; v1(87.6,35.1) 87.667,35.033 87.667,34.883 R81.2@88.05,34.5 ; v1@91.6,35.405 v1(91.6,35.5) U1.37@91.6,36.8
  Int2 (Sign) w0.15: v1(63.9,31.4) 63.925,31.425 63.925,36.593 65.11,37.778 65.11,42.19 v1(65.1,42.2)
  Int3 (Sign) w0.15: v1(15.2,46.3) 34.7,46.3 35.6,45.4 59.4,45.4 60.6,44.2 63.1,44.2 v1(65.1,42.2) ; v1(87.6,35.1) 87.6,39.6 85.8,41.4 85.8,47.4 86.125,47.725 86.125,49.825 87.4,51.1 87.4,52.4 88.175,53.175 88.175,62.03 87.725,62.48 87.725,66.725 88.9,67.9 v1(88.9,69.2)
  Bottom Layer w0.15: v1(63.9,31.4) 77.2,31.4 80.3,34.5 85.272,34.5 86.247,35.475 87.225,35.475 v1(87.6,35.1) 87.681,35.1 87.781,35 91.1,35 v1(91.6,35.5)
TB_MISO: R83.2 R103.1 U1.36 X11.7 X17.1 X18.5 | length 161
  Top Layer w0.15: X18.5@17.65,51.59 X18.5@17.7,51.64 19,52.94 R103.1@19,59.6 ; X11.7@64.6,36 X11.7@64.635,35.965 64.93,35.67 64.93,34.17 v1(65.5,33.6) ; v1(78.8,67.9) 78.8,71.606 X17.1@79.076,71.882 ; v1(91.1,38) U1.36@91.1,36.8 91.1,35.328 91.403,35.025 92.525,35.025 R83.2@93.05,34.5
  Int2 (Sign) w0.15: X18.5@17.7,51.64 20.94,48.4 36.6,48.4 40.9,44.1 v1(40.9,33.5) ; v1(91.1,38) 91.1,36.672 93.242,34.53 v1(93.242,29.525)
  Int3 (Sign) w0.15: v1(40.9,33.5) 51.85,33.5 52.125,33.225 64.225,33.225 64.6,33.6 v1(65.5,33.6) 77.9,33.6 v1(79.6,31.9) ; v1(88.2,66.1) 89.4,64.9 89.4,57.2 88.925,56.725 88.925,55.875 89.625,55.175 89.625,50.975 91.1,49.5 v1(91.1,38)
  Bottom Layer w0.15: v1(78.8,67.9) 80.6,66.1 v1(88.2,66.1) ; v1(79.6,31.9) 80.608,31.9 80.683,31.975 86.449,31.975 88.624,29.8 89.728,29.8 89.903,29.975 91.271,29.975 91.721,29.525 v1(93.242,29.525)
TB_MOSI: R82.2 R104.1 U1.35 X11.6 X17.3 X18.6 | length 135.3
  Top Layer w0.15: v1(20.2,45.8) 20.22,45.82 20.22,51.62 21.5,52.9 21.5,59.55 R104.1@21.45,59.6 ; v1(62.7,33.8) 62.7,38.345 63.365,39.01 X11.6@63.365,40.035 63.4,40.07 v1(63.4,42.2) ; R82.2@90.45,34.5 90.45,35.255 ; v1(90.6,35.5) U1.35@90.6,36.8
  Int2 (Sign) w0.15: X17.3@81.616,71.882 81.5,71.766 81.5,49.972 81.9,49.572 81.9,37.1 v1(82.9,36.1)
  Int3 (Sign) w0.15: v1(20.2,45.8) 34.6,45.8 36.1,44.3 59.9,44.3 60.429,43.771 61.829,43.771 v1(63.4,42.2) ; v1(62.7,33.8) 64.9,36 v1(71.1,36)
  Bottom Layer w0.15: v1@71.1,36.05 82.85,36.05 v1(82.9,36.1) 90,36.1 v1(90.6,35.5)
TB_RESET#: U19.2 X11.10 | length 30.3
  Top Layer w0.15: v1(53.1,62) U19.2@54.896,62 ; X11.10@65.905,40.035 v1(65.905,42.175)
  Int2 (Sign) w0.15: v1(53.1,62) 55.5,59.6 57.6,59.6 63.3,53.9 63.3,53.2 64.475,52.025 64.475,48.725 65.905,47.295 v1(65.905,42.175)
TB_RX: U18.2 X11.11 X18.13 X29.1 | length 102.4
  Top Layer w0.15: U18.2@55,51.5 55.605,51.5 56.9,50.205 v1(56.9,47.9) 59.275,45.525 59.275,38.835 X29.1@55.64,35.2 ; X11.11@67.175,35.965 v1(67.175,38.105)
  Int2 (Sign) w0.15: X18.13@15.16,74.5 15.16,63.189 16.5,61.849 v1(16.5,48.5)
  Int3 (Sign) w0.15: v1(16.5,48.5) 17.1,47.9 v1(56.9,47.9)
  Bottom Layer w0.15: X29.1@55.64,35.2 59.568,35.2 62.948,38.58 66.7,38.58 v1(67.175,38.105)
TB_SEL0: R87.2 R145.1 U1.38 X11.9 X17.7 X18.3 | length 153.5
  Top Layer w0.15: v1(12.6,45.8) 12.61,45.81 12.61,51.63 X18.3@12.62,51.64 ; R145.1@65.13,32.3 65.345,32.085 65.345,31.955 65.8,31.5 69.1,31.5 69.7,32.1 v1(69.7,34.8) ; R145.1@65.13,32.32 65.975,33.165 65.975,35.895 X11.9@65.905,35.965 ; v1(92.1,38) U1.38@92.1,36.8 92.159,36.741 92.159,35.941 92.5,35.6 93.219,35.6 93.305,35.514 93.414,35.514 93.903,35.025 95.175,35.025 95.4,34.8 95.95,34.8 R87.2@96.05,34.7
  Int2 (Sign) w0.15: v1(69.7,34.8) v1(69.7,40.6) ; v1(90.6,69.5) 91.3,68.8 91.3,67.3 90.6,66.6 90.6,57.2 91.1,56.7 91.1,47.6 92.6,46.1 92.6,42.128 93.475,41.253 93.475,40.233 92.1,38.858 v1(92.1,38)
  Int3 (Sign) w0.15: v1(12.6,45.8) 18.628,45.8 19.128,45.3 34.676,45.3 36.076,43.9 59.7,43.9 60.225,43.375 61.567,43.375 64.342,40.6 v1(69.7,40.6)
  Bottom Layer w0.15: v1(69.7,34.8) 69.7,35.7 70.525,36.525 78.425,36.525 78.5,36.6 89.924,36.6 90.324,36.2 91.572,36.2 92.272,35.5 v1(93.4,35.5) ; X17.7@86.696,71.882 88.678,69.9 90.2,69.9 v1(90.6,69.5)
TB_SWCLK_TCLK: U17.4 X11.4 | length 22.2
  Top Layer w0.15: U17.4@55,57.7 57.728,57.7 58.028,57.4 v1(58.1,57.4) ; X11.4@62.095,40.035 v1(62.095,42.175)
  Bottom Layer w0.15: v1(58.1,57.4) 58.7,56.8 58.7,49.222 62.095,45.827 v1(62.095,42.175)
TB_SWDCLK/JTAG_CLK: R127.1 U1.16 U17.6 | length 56.2
  Top Layer w0.15: v1(46.5,58.5) 47.035,59.035 48.455,59.035 48.97,58.52 48.97,58.48 49.185,58.265 49.208,58.265 49.273,58.2 U17.6@50.6,58.2 U17.6@50.705,58.2 ; U1.16@81.7,40.7 81.725,40.725 83.775,40.725 v1(83.8,40.7)
  Int3 (Sign) w0.15: v1(46.5,58.5) 47.2,57.8 47.8,57.8 50.2,55.4 75.2,55.4 79.1,51.5 80.8,51.5 82.4,49.9 82.4,42.1 v1(83.8,40.7)
TB_SWDIO/JTAG_SWDIO/TMS: R70.1 U1.17 U17.10 | length 49.1
  Top Layer w0.15: v1(49,55) 49,55.97 R70.1@48.97,56 49.5,56 49.7,56.2 U17.10@50.6,56.2 ; U1.17@81.7,40.2 v1(83,40.2)
  Int3 (Sign) w0.15: v1(49,55) 75,55 78.9,51.1 80.6,51.1 82,49.7 82,41.2 v1(83,40.2)
TB_SWDIO_TMS: U17.2 X11.2 | length 19.9
  Top Layer w0.15: U17.2@54.896,56.7 v1(56.1,56.7) ; X11.2@60.825,40.035 v1(60.825,42.175)
  Bottom Layer w0.15: v1(56.1,56.7) 56.1,46.828 60.753,42.175 v1(60.825,42.175)
TB_TX: U18.4 X11.12 X18.14 X29.2 | length 107.8
  Top Layer w0.15: U18.4@55.605,52.5 U18.4@55,52.5 54.971,52.471 53.571,52.471 52.725,51.625 52.725,48.875 v1(53.2,48.4) 53.2,35.3 X29.2@53.1,35.2 54.225,34.075 56.604,34.075 59.575,37.046 59.575,41.597 60.678,42.7 66.3,42.7 67.175,41.825 X11.12@67.175,40.035
  Int2 (Sign) w0.15: X18.14@12.62,74.5 12.62,57.08 13.9,55.8 v1(13.9,50)
  Int3 (Sign) w0.15: v1(13.9,50) 16.2,50 17.8,48.4 v1(53.2,48.4)
TB_UART_Rx: R150.2 U1.21 U18.6 X17.17 | length 110.3
  Top Layer w0.15: R150.2@48.47,53.2 49.163,53.2 49.355,53.008 v1(49.401,53.008) 49.405,53.004 50.596,53.004 U18.6@50.6,53 ; v1(82.9,37.1) 83.525,37.1 83.6,37.025 U1.21@83.6,36.8 ; v1(85.3,73) 85.307,73.007 91.952,73.007 92.42,73.475 93.672,73.475 93.947,73.2 98.078,73.2 X17.17@99.396,71.882
  Int2 (Sign) w0.15: v1(47.4,36.6) 47.4,51.007 v1(49.401,53.008) ; v1(82.9,37.1) 82.4,37.6 82.4,49.496 81.8,50.096 81.8,68.472 83.028,69.7 84.2,69.7 85.3,70.8 v1(85.3,73)
  Int3 (Sign) w0.15: v1(47.4,36.6) 65.7,36.6 66.675,37.575 73.025,37.575 73.9,36.7 78.3,36.7 78.7,37.1 v1(82.9,37.1)
TB_UART_Tx: R152.2 U1.22 U18.10 X17.19 | length 100.4
  Top Layer w0.15: R152.2@48.47,49.5 50.5,49.5 ; v1(50.5,37.5) 50.5,49.5 ; U18.10@50.5,51.025 50.5,49.5 ; v1(83,38.6) 83.4,38.6 84.1,37.9 U1.22@84.1,36.8 ; v1(86.9,69.7) 87.9,70.7 100.6,70.7 101.782,71.882 X17.19@101.936,71.882
  Int2 (Sign) w0.15: v1(83,38.6) 83.5,38.6 84.475,39.575 84.475,44.843 84.125,45.193 84.125,50.725 84.625,51.225 84.625,67.42 86.9,69.695 v1(86.9,69.7)
  Int3 (Sign) w0.15: v1(50.5,37.5) 50.538,37.5 50.738,37.3 64.6,37.3 65.9,38.6 v1(83,38.6)
TRACE_CLOCK: R15.2 R25.2 X1.12 | length 6.3
  Top Layer w0.15: R15.2@86.45,32.5 R25.2@86.45,31.5 87.166,30.784 87.166,30.234 87.425,29.975 87.925,29.975 88.168,29.732 88.168,29.327 88.935,28.56 X1.12@88.935,27.535
TRACE_DATA_0: R12.2 X1.14 | length 3.6
  Top Layer w0.15: R12.2@88.95,30.5 88.9,30.45 88.9,29.8 89.845,28.855 89.91,28.855 90.205,28.56 X1.14@90.205,27.535
TRACE_DATA_1: R17.2 X1.16 | length 2.9
  Top Layer w0.15: R17.2@91.35,30.35 91.475,30.225 X1.16@91.475,27.535
TRACE_DATA_2: R72.2 X1.18 | length 4.4
  Top Layer w0.15: X1.18@92.745,27.535 92.745,29.7 93.95,30.905 R72.2@93.95,31.4
TRACE_DATA_3: R26.2 X1.20 | length 5.8
  Top Layer w0.15: X1.20@94.015,27.535 95.035,27.535 96.2,28.7 96.2,30.75 96.425,30.975 96.443,30.975 96.575,31.107 96.575,31.125 R26.2@96.95,31.5
USB_D_N: R19.2 U7.3 | length 12.6
  Top Layer w0.2: R19.2@14.7,33.03 14.68,33.03 14.49,32.84 14.49,32.82 14.2,32.53 14.2,32 13.7,31.5 13.7,22.5 14.467,21.733 14.983,21.733 U7.3@15,21.75
USB_D_P: R20.2 U7.4 | length 13.2
  Top Layer w0.2: R20.2@13.5,33.03 13.52,33.03 13.71,32.84 13.71,32.813 13.8,32.723 13.8,32.166 13.3,31.666 13.3,22.334 14.334,21.3 14.95,21.3 U7.4@15,21.25
USB_DS_N: R19.1 X10.A7 X10.B7 | length 9.1
  Top Layer w0.2: X10.A7@11.75,35.27 11.77,35.25 12.719,35.25 12.919,35.45 14.05,35.45 v1(14.6,34.9) 14.6,34.883 14.3,34.583 14.3,34.277 14.417,34.16 14.51,34.16 R19.1@14.7,33.97
  Bottom Layer w0.2: X10.B7@10.38,35.9 10.493,35.9 10.718,35.675 13.063,35.675 13.237,35.5 14,35.5 v1(14.6,34.9) ; X10.B7@10.45,35.87 X10.B7@10.494,35.87
USB_DS_P: R20.1 X10.A6 X10.B6 | length 8.1
  Top Layer w0.2: X10.A6@11.63,35.75 11.68,35.8 12.526,35.8 12.726,36 v1(13.7,36) ; R20.1@13.5,33.97 13.69,34.16 13.783,34.16 13.9,34.277 13.9,34.633 13.7,34.833 v1(13.7,34.9)
  Int3 (Sign) w0.2: v1(13.7,34.9) v1(13.7,36)
  Bottom Layer w0.2: X10.B6@10.38,35.1 10.493,35.1 10.718,35.325 12.918,35.325 13.186,35.057 13.449,35.057 13.605,34.9 v1(13.7,34.9)
USBSHLD: L1.2 X10.S1 X10.S2 X10.S3 X10.S4 X10.S5 X10.S6 | length 25.2
  Top Layer w0.5: X10.S6@4.12,35.47 X10.S5@7.12,35.47 ; X10.S4@4.5,31.23 4.5,29.7 5.1,29.1 L1.2@6.2,29.1 L1.2@6.185,29.085 ; X10.S2@9.245,39.785 X10.S2@9.23,39.77 9.23,39.931 X10.S2@9.3,40.001 ; X10.S3@9.3,31.2 4.57,31.2 4.57,33.13 4.02,33.68 4.02,37.32 4.57,37.87 4.57,39.74 X10.S2@9.3,39.74
"User LED1": D1.2 U1.4 | length 81.5
  Top Layer w0.15: v1(48,2.5) D1.2@49.05,2.5 ; v1(80.4,46.7) U1.4@81.7,46.7
  Int2 (Sign) w0.15: v1(48,2.5) 48.7,3.2 56.3,3.2 58.4,5.3 58.4,20.4 60.9,22.9 60.9,26.5 59.5,27.9 v1(59.5,49.3)
  Bottom Layer w0.15: v1(59.5,49.3) 62.1,46.7 v1(80.4,46.7)
"User LED2": D2.2 U1.5 | length 77
  Top Layer w0.15: v1(56.2,2.5) D2.2@57.15,2.5 ; U1.5@81.7,46.2 v1(83,46.2)
  Int2 (Sign) w0.15: v1(56.2,2.5) 58.8,5.1 58.8,20.3 61.3,22.8 61.3,26.8 60,28.1 v1(60,50)
  Bottom Layer w0.15: v1(60,50) 62.8,47.2 82,47.2 v1(83,46.2)
User_switch: R51.2 U1.33 X16.23 | length 79.7
  Top Layer w0.15: R51.2@58.87,6.8 v1(59.7,6.8) ; v1(89.6,35.5) U1.33@89.6,36.8
  Int2 (Sign) w0.15: v1(89.6,35.5) 89.6,35.462 89.825,35.237 89.825,35.075 90.6,34.3 90.6,27 89.8,26.2 89.8,22.947 90,22.747 v1(90,20) ; X16.23@106.8,11.1 106.978,10.922 X16.23@107.016,10.922
  Bottom Layer w0.15: v1(59.7,6.8) 63.6,10.7 72,10.7 81.3,20 ; 84.4,20 81.3,20 ; X16.23@107.016,10.922 105.831,12.107 105.831,13.698 99.654,19.875 92.683,19.875 92.208,19.4 90.6,19.4 v1(90,20) 81.3,20
V5V: Q2.4 Q3.2 Q4.2 Q5.4 Q6.2 Q7.4 TP6.1 X20.3 | length 69.7
  Top Layer w0.3: v1(50.2,65.6) Q7.4@50.2,66.5 ; v1(50.2,69.9) Q5.4@50.2,70.8 ; v1(50.2,74.2) Q2.4@50.2,75.1 ; v1(50.9,65.6) 50.9,66.483 50.882,66.5 ; v1(50.9,69.9) 50.9,70.783 50.882,70.8 ; v1(50.9,74.2) 50.9,75.083 50.882,75.1 ; v1(51.6,65.6) 51.6,66.435 Q6.2@51.615,66.45 ; v1(51.6,69.9) 51.6,70.735 Q4.2@51.615,70.75 ; v1(51.6,74.2) 51.6,75.035 Q3.2@51.615,75.05 ; Q4.2@51.615,70.55 Q4.2@51.64,70.525 ; Q6.2@51.665,66.5 Q6.2@51.615,66.45 ; Q4.2@51.665,70.8 Q4.2@51.615,70.75 ; Q3.2@51.665,75.1 Q3.2@51.615,75.05 ; Q7.4@50.2,66.5 50.15,66.55 Q7.4@49.95,66.55 50,66.5 Q7.4@50.2,66.5 ; Q7.4@50.2,66.5 50.882,66.5 ; Q5.4@50.2,70.8 50.15,70.85 Q5.4@49.95,70.85 50,70.8 Q5.4@50.2,70.8 ; Q5.4@50.2,70.8 50.882,70.8 ; Q2.4@50.2,75.1 50.882,75.1 ; Q2.4@50.2,75.1 50,75.1 Q2.4@49.95,75.15 50.15,75.15 Q2.4@50.2,75.1 ; 50.882,66.5 51.565,66.5 Q6.2@51.615,66.45 ; 50.882,70.8 51.565,70.8 Q4.2@51.615,70.75 ; 50.882,75.1 51.565,75.1 Q3.2@51.615,75.05
  Top Layer w0.5: X20.3@33,67.04 40.46,67.04 TP6.1@43,64.5
  Bottom Layer w2: X20.3@33,67.04 41.06,67.04 ; v1(51.6,65.6) v1(50.9,65.6) v1(50.2,65.6) 42.5,65.6 41.06,67.04 ; v1(51.6,69.9) v1(50.9,69.9) v1(50.2,69.9) 42.5,69.9 ; v1(51.6,74.2) v1(50.9,74.2) v1(50.2,74.2) 43.7,74.2 42.5,73 42.5,69.9 ; 41.06,67.04 42.5,68.48 42.5,69.9
VBUS_C: D21.2 R22.2 TP3.1 X10.A4 X10.A9 X10.B4 X10.B9 | length 33.1
  Top Layer w0.2: X10.B4@10.45,34.27 X10.B4@10.475,34.245 ; X10.A9@11.675,34.245 X10.A9@11.7,34.22
  Top Layer w0.3: X10.B9@10.38,36.7 10.43,36.75 X10.A4@11.63,36.75 ; X10.B4@10.475,34.245 X10.A9@11.675,34.245
  Top Layer w0.5: TP3.1@6,19.365 TP3.1@6,19.5 6.135,19.5 6.293,19.342 R22.2@7.802,19.342 R22.2@7.802,19.342 ; R22.2@7.752,19.292 R22.2@7.802,19.342 ; v1(7.8,18.602) v1(7.8,18.602) R22.2@7.802,19.342 ; D21.2@13.6,39 D21.2@13.7,39
  Int3 (Sign) w0.5: v1(7.8,18.602) 7.8,26.5 11.4,30.1 11.4,30.9 12.2,31.7 12.2,34.3 X10.B4@10.38,34.3 ; X10.B9@10.38,36.7 12.2,36.7
  Int3 (Sign) w1: 12.2,34.3 12.2,36.7 12.9,37.4 v2(12.9,39.8) v2(13.6,39.8)
Vbus_PFC: R40.2 R147.2 U1.70 | length 17.4
  Top Layer w0.15: v1(88.6,48.9) U1.70@88.6,50.2 ; v1(88.65,61.4) 89.79,61.4 90.47,62.08 R40.2@90.47,62.1 R147.2@91.53,62.1
  Int2 (Sign) w0.15: v1(88.6,48.9) 88.6,53.054 88.175,53.479 88.175,60.925 v1(88.65,61.4)
VDCDC5: C126.2 C127.2 C128.2 R131.2 TP9.1 U14.1 X20.1 | length 23.6
  Top Layer w0.5: C127.2@39.16,59.49 39.8,58.85 39.8,57.95 C128.2@40.15,57.6 ; 39.2,61.803 TP9.1@42.997,61.803 ; U14.1@40.605,54.045 40.605,54.375 39.24,55.74 39.2,55.74 C126.2@39.14,55.8 39.155,55.8 39.215,55.86 39.215,56.365 40.15,57.3 C128.2@40.15,57.6 ; R131.2@42,54.97 42,57.2 41.6,57.6 C128.2@40.15,57.6
  Top Layer w1: X20.1@33,61.96 39.2,61.96 39.2,61.803 39.2,59.9 C127.2@39.2,59.49
VDCDC7: C80.2 C129.2 C130.2 U14.5 U14.8 U20.5 | length 14.1
  Top Layer w0.5: U14.5@36.795,48.355 36.795,48.025 37.82,47 40,47 ; U20.5@38.51,39.755 38.51,40.4 38.76,40.65 39.125,40.65 40.2,41.725 C80.2@40.2,41.8 ; C80.2@40.2,42.4 40.2,42.55 39.875,42.875 39.725,42.875 39.18,43.42 39.18,43.747 39.115,43.812 39.115,44.465 40.05,45.4 C130.2@40.05,45.7 40,45.75 40,47 ; U14.8@40.605,48.355 40.53,48.28 40.53,47.95 40,47.42 40,47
